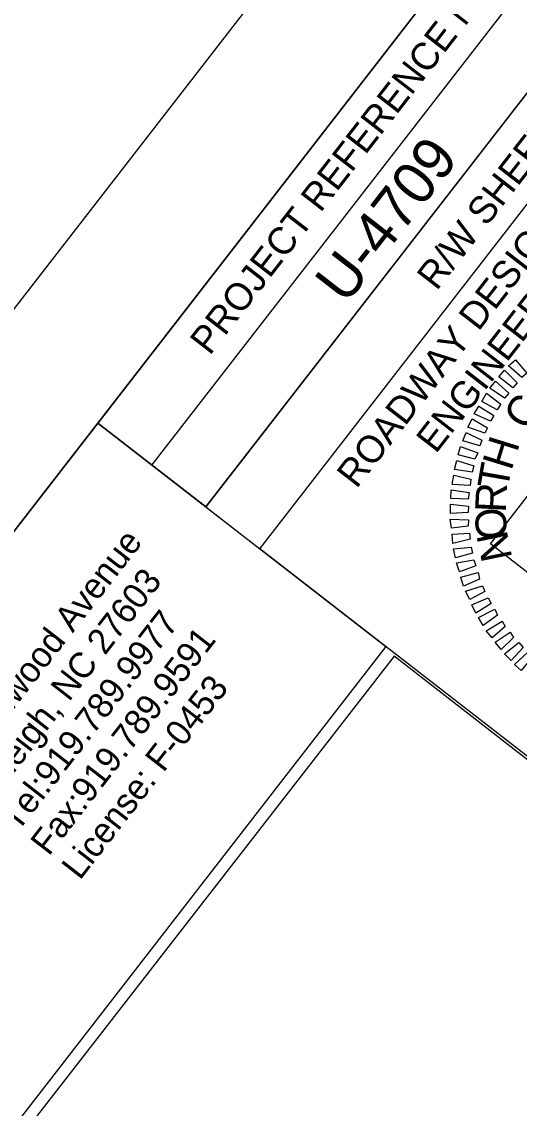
# Model space of a CAD drawing. Extents: x 2013373 to 2015284, y 444589 to 446636.
# Drawn here: x 2014282.4 to 2014373.4, y 446317 to 446515.8 of the extents above; entities that cross this region are included whole.
import ezdxf

# ---------------------------------------------------------------- set-up
doc = ezdxf.new("R2010")
doc.units = 0
for name, color, linetype in [('Old_Level_2', 7, 'Continuous'), ('Old_Level_58', 7, 'Continuous'), ('Sheet Clip Boundary CELL', 7, 'Continuous'), ('Sheet Data Field CELL', 7, 'Continuous'), ('Sheet Plan And Profile CELL', 7, 'Continuous'), ('Sheet Plot Border Outside CELL', 7, 'Continuous'), ('Sheet Professional Seal CELL', 7, 'Continuous'), ('Sheet Sticker Incomplete CELL', 7, 'Continuous')]:
    doc.layers.add(name, color=color, linetype=linetype)

msp = doc.modelspace()

# ---------------------------------------------------------------- linework, layer by layer
at = {"layer": 'Old_Level_58'}
msp.add_lwpolyline([(2014173.74, 446284.27), (2014296.33, 446442.35), (2014349.03, 446401.48), (2014226.44, 446243.4)], close=True, dxfattribs=at)
at = {"layer": 'Sheet Clip Boundary CELL'}
msp.add_lwpolyline([(2014175.88, 446280.17), (2013513.08, 445427.57), (2013603.78, 445375.37), (2013612.37, 445329.9), (2013915.76, 445258.44), (2014041.96, 445083.42), (2014361.11, 444814.86), (2015247.44, 445957.73), (2014564.17, 446487.44), (2014441.59, 446328.91), (2014350.55, 446399.68), (2014226.85, 446240.55)], close=True, dxfattribs=at)
at = {"layer": 'Sheet Plan And Profile CELL'}
for p, q in [((2014306.25, 446434.66), (2014428.85, 446592.74)), ((2014316.13, 446427), (2014438.73, 446585.08)), ((2014316.13, 446427), (2014326.01, 446419.34))]:
    msp.add_line(p, q, dxfattribs=at)
for points in [[(2014418.93, 446600.43), (2013499.68, 445415.12), (2014329.4, 444771.64), (2015248.65, 445956.96)], [(2014296.33, 446442.35), (2014418.93, 446600.43), (2014438.73, 446585.08), (2014316.13, 446427)], [(2014326.01, 446419.34), (2014387.32, 446498.4), (2014476.22, 446429.46), (2014414.9, 446350.4)]]:
    msp.add_lwpolyline(points, close=True, dxfattribs=at)
at = {"layer": 'Sheet Plot Border Outside CELL'}
msp.add_lwpolyline([(2014241.91, 444618.03), (2015283.73, 445961.39), (2014414.5, 446635.51), (2013372.67, 445292.15)], close=True, dxfattribs=at)
at = {"layer": 'Sheet Professional Seal CELL'}
for points in [[(2014373.93, 446450.66), (2014371.48, 446452.81), (2014372.73, 446453.93), (2014374.82, 446451.49)], [(2014372.28, 446448.78), (2014369.71, 446450.77), (2014370.76, 446452.04), (2014373.05, 446449.7)], [(2014370.77, 446446.91), (2014368.05, 446448.71), (2014369.1, 446449.98), (2014371.54, 446447.83)], [(2014369.43, 446444.78), (2014366.57, 446446.31), (2014367.45, 446447.78), (2014370.05, 446445.82)], [(2014368.2, 446442.7), (2014365.18, 446444.03), (2014366.07, 446445.43), (2014368.82, 446443.74)], [(2014367.16, 446440.47), (2014364.03, 446441.57), (2014364.8, 446443.13), (2014367.61, 446441.45)], [(2014366.21, 446438.18), (2014363.13, 446439.1), (2014363.72, 446440.61), (2014366.57, 446439.22)], [(2014365.34, 446435.75), (2014362.25, 446436.5), (2014362.69, 446438.05), (2014365.87, 446436.92)], [(2014364.82, 446433.37), (2014361.62, 446433.82), (2014362.02, 446435.47), (2014365.14, 446434.51)], [(2014364.45, 446430.93), (2014361.18, 446431.13), (2014361.5, 446432.84), (2014364.56, 446432.05)], [(2014364.09, 446428.43), (2014360.94, 446428.53), (2014360.99, 446430.14), (2014364.29, 446429.66)], [(2014364.11, 446426.01), (2014360.89, 446425.78), (2014360.89, 446427.49), (2014364.18, 446427.16)], [(2014364.11, 446423.48), (2014361.02, 446423.09), (2014360.81, 446424.77), (2014364.14, 446424.66)], [(2014364.48, 446421.1), (2014361.3, 446420.34), (2014361.15, 446422.03), (2014364.34, 446422.22)], [(2014364.91, 446418.55), (2014361.77, 446417.69), (2014361.42, 446419.36), (2014364.63, 446419.66)], [(2014365.49, 446416.2), (2014362.49, 446415.11), (2014361.93, 446416.75), (2014365.14, 446417.3)], [(2014366.15, 446413.79), (2014363.25, 446412.5), (2014362.76, 446414.15), (2014365.93, 446414.98)], [(2014367.12, 446411.53), (2014364.38, 446410.04), (2014363.62, 446411.58), (2014366.73, 446412.58)], [(2014368.32, 446409.33), (2014365.51, 446407.58), (2014364.75, 446409.12), (2014367.76, 446410.4)], [(2014369.45, 446407.19), (2014366.83, 446405.29), (2014366.01, 446406.75), (2014368.95, 446408.27)], [(2014370.88, 446405.13), (2014368.47, 446403.07), (2014367.38, 446404.36), (2014370.3, 446406.08)], [(2014372.38, 446403.14), (2014370.16, 446400.94), (2014369.04, 446402.25), (2014371.8, 446404.1)], [(2014374.15, 446401.26), (2014371.95, 446398.92), (2014370.73, 446400.12), (2014373.36, 446402.19)], [(2014375.89, 446399.59), (2014373.82, 446397.09), (2014372.58, 446398.18), (2014375.01, 446400.41)]]:
    msp.add_lwpolyline(points, close=True, dxfattribs=at)
at = {"layer": 'Sheet Sticker Incomplete CELL'}
msp.add_lwpolyline([(2014386.73, 446405.85), (2014368.16, 446420.25), (2014458.24, 446536.41), (2014476.81, 446522.01)], close=True, dxfattribs=at)

# ---------------------------------------------------------------- texts
at = {"layer": 'Old_Level_2'}
for s, p in [('1 Glenwood Avenue', (2014270.31, 446376.22)), ('Raleigh, NC 27603', (2014276, 446371.81)), ('Tel:919.789.9977 ', (2014281.69, 446367.4)), ('Fax:919.789.9591', (2014287.37, 446362.99)), ('License: F-0453', (2014293.06, 446358.58))]:
    msp.add_text(s, height=4.6576, rotation=52.2051, dxfattribs=at).set_placement(p)
at = {"layer": 'Sheet Data Field CELL'}
msp.add_text('U-4709', height=7.75, rotation=52.2051, dxfattribs=at).set_placement((2014341.73, 446463.84))
at = {"layer": 'Sheet Plan And Profile CELL'}
for s, height, p in [('PROJECT REFERENCE NO.', 5.0001, (2014316.81, 446454.56)), ('R/W SHEET NO.', 5.0001, (2014358.33, 446466.4)), ('ROADWAY DESIGN', 5.0001, (2014343.66, 446430.2)), ('ENGINEER', 5, (2014358.18, 446436.59))]:
    msp.add_text(s, height=height, rotation=52.2051, dxfattribs=at).set_placement(p)
at = {"layer": 'Sheet Professional Seal CELL'}
for s, rotation, p in [('C', 58.425, (2014375.08, 446440.72)), ('H', 72.8246, (2014372, 446433.49)), ('T', 80.0249, (2014371.31, 446429.91)), ('R', 87.2256, (2014370.97, 446425.88)), ('O', 94.4268, (2014371.3, 446421.25)), ('N', 101.6286, (2014372.19, 446417.66))]:
    msp.add_text(s, height=5.64, rotation=rotation, dxfattribs=at).set_placement(p)

doc.saveas('drawing.dxf')
